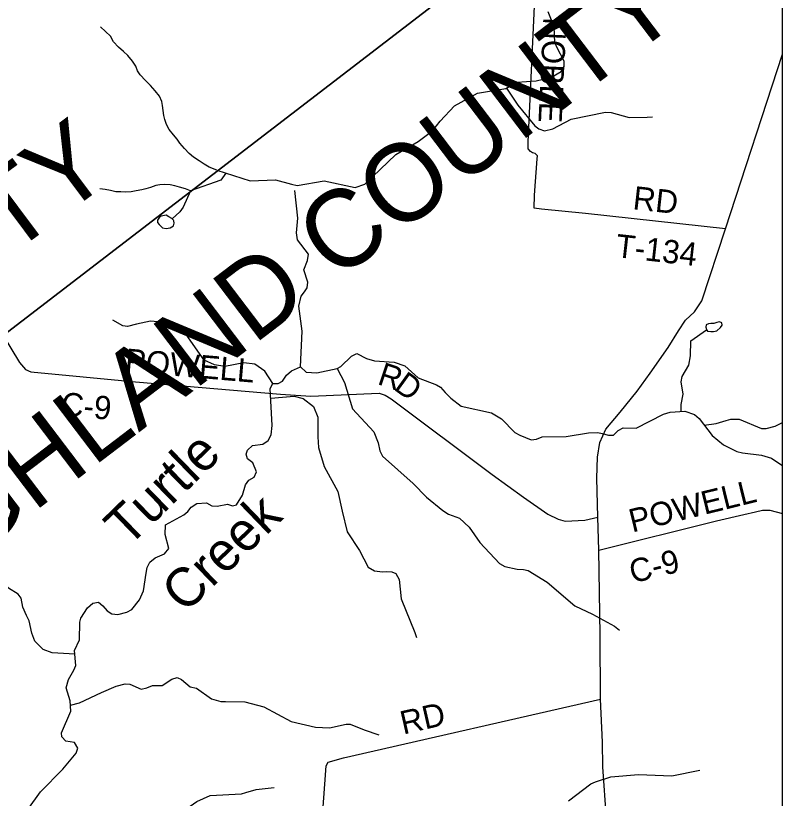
# Model space of a CAD drawing. Extents: x 0 to 1052, y -194 to 246.
# Drawn here: x 6.909 to 8.782, y 17.846 to 19.757 of the extents above; entities that cross this region are included whole.
import ezdxf

# ---------------------------------------------------------------- set-up
doc = ezdxf.new("R2010")
doc.units = 0
for name, color, linetype in [('GM_X_Corporation', 7, 'Continuous'), ('GM_X_County_Road', 7, 'Continuous'), ('GM_X_County_Road_Text', 7, 'Continuous'), ('GM_X_County_Text', 7, 'Continuous'), ('GM_X_Minor_Lake', 7, 'Continuous'), ('GM_X_Minor_River', 7, 'Continuous'), ('GM_X_Minor_River_Text', 7, 'Continuous'), ('GM_X_Township_Road', 7, 'Continuous'), ('GM_X_Township_Road_Text', 7, 'Continuous')]:
    doc.layers.add(name, color=color, linetype=linetype)

msp = doc.modelspace()

# ---------------------------------------------------------------- linework, layer by layer
at = {"layer": 'GM_X_Corporation'}
for points in [[(5.1788, 17.6981), (5.491, 17.9457), (6.1888, 18.4644), (6.5994, 18.7694), (6.8785, 18.9763), (8.1871, 19.9814), (8.6571, 20.341), (8.7822, 20.435), (8.7822, 21.0055), (1.9822, 21.0055), (1.9822, 14.2055)], [(8.7822, 14.2055), (8.7822, 20.435), (8.6571, 20.341), (8.1871, 19.9814), (6.8785, 18.9763), (6.5994, 18.7694), (6.1888, 18.4644), (5.491, 17.9457), (5.1788, 17.6981)], [(8.7822, 14.2055), (8.7822, 19.8853), (8.7716, 19.9458), (8.7665, 19.9791), (8.7595, 20.0343), (8.7564, 20.0663), (8.7504, 20.1046), (8.7444, 20.1332), (8.7375, 20.1583), (8.7292, 20.1831), (8.7137, 20.2216), (8.6781, 20.298), (8.6571, 20.341), (8.1871, 19.9814), (6.8785, 18.9763), (6.5994, 18.7694), (6.1888, 18.4644), (5.491, 17.9457), (5.1788, 17.6981)]]:
    msp.add_lwpolyline(points, dxfattribs=at)
msp.add_lwpolyline([(8.7822, 20.435), (8.7822, 21.0055), (5.5898, 21.0055), (5.6935, 20.5776), (5.9283, 19.6076), (5.992, 19.3448), (6.152, 18.6129), (6.1888, 18.4644), (6.5994, 18.7694), (6.8785, 18.9763), (8.1871, 19.9814), (8.6571, 20.341)], close=True, dxfattribs=at)
at = {"layer": 'GM_X_County_Road'}
msp.add_line((8.3338, 18.4518), (8.3315, 18.5323), dxfattribs=at)
for points in [[(8.3315, 18.5323), (8.329, 18.6276), (8.3307, 18.6788), (8.3358, 18.7147), (8.3511, 18.747), (8.3856, 18.7889), (8.4271, 18.8402), (8.4594, 18.8845), (8.5028, 18.9464), (8.5285, 18.9878), (8.5459, 19.0136), (8.5673, 19.0339), (8.5855, 19.0607), (8.6429, 19.2363), (8.7822, 19.6626)], [(6.8787, 18.9758), (6.9182, 18.9098), (6.933, 18.8934), (6.9457, 18.887), (7.2015, 18.8628), (7.5559, 18.8325), (7.6301, 18.8283), (7.7972, 18.8349), (7.8119, 18.8307), (7.8261, 18.8212), (8.0731, 18.6363), (8.1498, 18.5811), (8.209, 18.5397), (8.2345, 18.5273), (8.2518, 18.523), (8.2997, 18.5255), (8.3315, 18.5323)], [(8.3338, 18.4518), (8.6214, 18.5235), (8.6882, 18.5392), (8.7168, 18.5452), (8.734, 18.5493), (8.7514, 18.5496), (8.7822, 18.5411)], [(8.4426, 17.3326), (8.4083, 17.4853), (8.3741, 17.6521), (8.3656, 17.7047), (8.3552, 17.7703), (8.3521, 17.7958), (8.3437, 17.9231), (8.3426, 17.9831), (8.3378, 18.088), (8.3374, 18.2452), (8.3338, 18.4518)]]:
    msp.add_lwpolyline(points, dxfattribs=at)
at = {"layer": 'GM_X_Minor_Lake'}
for points in [[(7.2901, 19.2618), (7.2829, 19.2661), (7.2769, 19.2696), (7.2647, 19.2675), (7.2601, 19.2649), (7.2555, 19.2578), (7.2558, 19.2517), (7.2599, 19.2467), (7.2677, 19.239), (7.2768, 19.237), (7.2863, 19.2391), (7.2943, 19.2435), (7.2959, 19.2503)], [(7.2959, 19.2503), (7.2956, 19.2557), (7.2947, 19.2578), (7.2901, 19.2618)], [(8.5992, 18.9869), (8.6071, 18.9857), (8.6139, 18.9856), (8.6219, 18.9877), (8.6312, 18.9959), (8.6354, 19.0012), (8.634, 19.0073), (8.6283, 19.0096), (8.6222, 19.0074), (8.6146, 19.0057), (8.6078, 19.0054), (8.6013, 19.0047), (8.5964, 19.0018), (8.5955, 18.9961)], [(8.5955, 18.9961), (8.5965, 18.9903), (8.5975, 18.9889), (8.5992, 18.9869)]]:
    msp.add_lwpolyline(points, dxfattribs=at)
at = {"layer": 'GM_X_Minor_River'}
for points in [[(7.4008, 19.3794), (7.4818, 19.3533), (7.5437, 19.3561), (7.5829, 19.3452), (7.5965, 19.3424), (7.6627, 19.3538), (7.7383, 19.3371), (7.7619, 19.3459), (7.8374, 19.4179), (7.8921, 19.4493), (7.9285, 19.4764), (7.9459, 19.4996), (7.981, 19.5366), (8.0376, 19.5676), (8.1068, 19.5787), (8.1202, 19.5876), (8.1336, 19.5942), (8.181, 19.598), (8.218, 19.6069), (8.2417, 19.6206), (8.2487, 19.633), (8.2489, 19.6455), (8.2323, 19.678), (8.2265, 19.6913), (8.2244, 19.7293), (8.2102, 19.7659)], [(7.4008, 19.3794), (7.3819, 19.3872), (7.3694, 19.3945), (7.3574, 19.4026), (7.3438, 19.4111), (7.3325, 19.4203), (7.3212, 19.4325), (7.3103, 19.4459), (7.3032, 19.4554), (7.2942, 19.4658), (7.2837, 19.4788), (7.2773, 19.491), (7.2733, 19.5035), (7.2707, 19.5131), (7.2693, 19.5256), (7.2679, 19.5378), (7.2661, 19.5473), (7.2601, 19.5602), (7.25, 19.5732), (7.2387, 19.5862), (7.2259, 19.5985), (7.2135, 19.6123), (7.2068, 19.6226), (7.2023, 19.634), (7.1945, 19.6462), (7.1832, 19.66), (7.1723, 19.6692), (7.1602, 19.6799), (7.1482, 19.6933), (7.1404, 19.7067), (7.128, 19.7182), (7.1163, 19.73)], [(8.1082, 19.5796), (8.1357, 19.5388), (8.1774, 19.4881), (8.1872, 19.4803), (8.2007, 19.4759), (8.2213, 19.4806), (8.2664, 19.5045), (8.3497, 19.5214), (8.3641, 19.5208), (8.4075, 19.5084), (8.4515, 19.5092), (8.4648, 19.5101)], [(7.4221, 19.3725), (7.4098, 19.3555), (7.336, 19.3295)], [(7.336, 19.3295), (7.3237, 19.3342), (7.309, 19.3381), (7.2976, 19.3412), (7.2863, 19.3436), (7.2726, 19.3445), (7.2612, 19.3439), (7.2513, 19.342), (7.238, 19.3376), (7.227, 19.3339), (7.2171, 19.3321), (7.2034, 19.3296), (7.1909, 19.3267), (7.1783, 19.3256), (7.1655, 19.3265), (7.1537, 19.327), (7.1408, 19.3301), (7.1276, 19.3325), (7.1143, 19.3338)], [(7.336, 19.3295), (7.3182, 19.2894), (7.31, 19.2778), (7.2912, 19.2608)], [(7.6051, 18.8992), (7.6088, 18.9864), (7.601, 19.0476), (7.6063, 19.0722), (7.6145, 19.083), (7.6211, 19.0928), (7.6224, 19.1064), (7.6126, 19.1362), (7.6217, 19.1592), (7.6242, 19.1743), (7.5979, 19.21), (7.5951, 19.2271), (7.5983, 19.2623), (7.5907, 19.3299)], [(7.5374, 18.8589), (7.5178, 18.8888), (7.4934, 18.9059), (7.4661, 18.909), (7.4198, 18.9006), (7.3948, 18.9048), (7.3692, 18.9162), (7.3258, 18.9783), (7.3011, 18.9973), (7.2736, 19.0076), (7.238, 19.0112), (7.2041, 19.0041), (7.182, 18.9984), (7.1707, 18.9997), (7.1466, 19.0133)], [(8.5353, 18.791), (8.5353, 18.8078), (8.5402, 18.8331), (8.535, 18.8628), (8.5371, 18.876), (8.5535, 18.9034), (8.5576, 18.9265), (8.5586, 18.9633), (8.5969, 18.9896)], [(7.5261, 18.7195), (7.5328, 18.7335), (7.5354, 18.7566), (7.5308, 18.8469), (7.5374, 18.8589), (7.5503, 18.8591), (7.5606, 18.8643), (7.5703, 18.8793), (7.5826, 18.8901), (7.6051, 18.8992), (7.6186, 18.8869), (7.6444, 18.885), (7.6942, 18.8952), (7.7037, 18.9004), (7.7292, 18.9257), (7.7425, 18.932), (7.7659, 18.9199), (7.7855, 18.9146), (7.834, 18.9112), (7.8596, 18.9017), (7.8925, 18.8731), (7.937, 18.8554), (7.9467, 18.8499), (7.9583, 18.8365), (7.9721, 18.8234), (7.9972, 18.8036), (8.0713, 18.7873), (8.0957, 18.7729), (8.1289, 18.739), (8.1406, 18.7331), (8.1681, 18.7217), (8.1817, 18.7226), (8.1951, 18.7285), (8.2539, 18.7295), (8.3082, 18.7381), (8.3317, 18.7389), (8.3423, 18.7372), (8.357, 18.7324), (8.3699, 18.7326), (8.3811, 18.7442), (8.393, 18.7504), (8.4252, 18.7496), (8.4921, 18.7842), (8.5081, 18.7889), (8.5441, 18.7917), (8.5679, 18.7834), (8.5791, 18.7733), (8.6103, 18.7323), (8.638, 18.7095), (8.6708, 18.693), (8.6847, 18.6894), (8.7309, 18.6841), (8.7558, 18.6769), (8.7806, 18.6595), (8.7822, 18.658)], [(7.6942, 18.8952), (7.7126, 18.8611), (7.7317, 18.7971), (7.7843, 18.7409), (7.7945, 18.7139), (7.7987, 18.6941), (7.8053, 18.6814), (7.8805, 18.6147), (7.913, 18.5815), (7.9526, 18.5491), (7.9665, 18.5401), (7.9933, 18.5302), (8.0168, 18.5082), (8.0432, 18.4703), (8.0913, 18.4198), (8.1044, 18.4117), (8.1339, 18.4059), (8.1494, 18.4045), (8.1615, 18.4024), (8.2077, 18.3737), (8.275, 18.3157), (8.3179, 18.2957), (8.3721, 18.2668), (8.3841, 18.2564)], [(7.532, 18.8233), (7.5896, 18.8282), (7.6115, 18.8221), (7.6362, 18.8028), (7.6472, 18.7764), (7.6472, 18.7283), (7.6487, 18.7025), (7.6624, 18.656), (7.6959, 18.5948), (7.7065, 18.5468), (7.7186, 18.4966), (7.7486, 18.4513), (7.77, 18.4108), (7.7854, 18.4011), (7.8054, 18.3993), (7.8149, 18.3999), (7.8278, 18.3993), (7.838, 18.3946), (7.8461, 18.3804), (7.8507, 18.3333), (7.8839, 18.2513), (7.8886, 18.2387)], [(8.5913, 18.7573), (8.6203, 18.7609), (8.6446, 18.7689), (8.6564, 18.7718), (8.6765, 18.7714), (8.7312, 18.7494), (8.7422, 18.7488), (8.7642, 18.7545), (8.7822, 18.7634)], [(7.0535, 18.1981), (6.9981, 18.201), (6.9759, 18.2096), (6.9561, 18.2301), (6.9484, 18.2491), (6.9421, 18.2796), (6.9355, 18.2922), (6.9263, 18.3124), (6.9225, 18.3349), (6.9151, 18.3445), (6.8914, 18.3593), (6.8833, 18.3723), (6.869, 18.4559), (6.8525, 18.5101), (6.8344, 18.5437), (6.8018, 18.5928), (6.7929, 18.6267), (6.79, 18.64), (6.7834, 18.6731), (6.7881, 18.7367), (6.7861, 18.75)], [(6.939, 17.8192), (6.9692, 17.8616), (7.0243, 17.9176), (7.0568, 17.9565), (7.0612, 17.9686), (7.0523, 17.982), (7.0315, 17.9858), (7.0214, 17.9962), (7.0212, 18.006), (7.044, 18.0588), (7.0418, 18.0838), (7.0324, 18.1162), (7.038, 18.1362), (7.0509, 18.1592), (7.0556, 18.1701), (7.0528, 18.2069), (7.0646, 18.2333), (7.0653, 18.2758), (7.0681, 18.2856), (7.0844, 18.3111), (7.0975, 18.3227), (7.1112, 18.3247), (7.122, 18.3162), (7.1328, 18.3039), (7.1441, 18.2969), (7.1585, 18.2948), (7.1809, 18.3005), (7.1924, 18.3075), (7.2114, 18.3311), (7.2216, 18.3526), (7.2279, 18.3961), (7.23, 18.4094), (7.2371, 18.4225), (7.2501, 18.4329), (7.2727, 18.4432), (7.2835, 18.4559), (7.2738, 18.4902), (7.2753, 18.5137), (7.32, 18.5384), (7.3296, 18.5466), (7.3381, 18.5571), (7.3516, 18.566), (7.3751, 18.5675), (7.3882, 18.5605), (7.4015, 18.5592), (7.4262, 18.5645), (7.4387, 18.5601), (7.4482, 18.5626), (7.4634, 18.5866), (7.4706, 18.6116), (7.4783, 18.6228), (7.4917, 18.6302), (7.4972, 18.643), (7.4881, 18.6648), (7.4757, 18.6748), (7.4721, 18.6863), (7.4757, 18.6961), (7.4872, 18.7073), (7.5127, 18.7107), (7.5261, 18.7195)], [(7.0427, 18.0734), (7.0652, 18.0793), (7.1183, 18.1046), (7.1546, 18.12), (7.1766, 18.1253), (7.188, 18.1244), (7.2159, 18.113), (7.2292, 18.1158), (7.2429, 18.1217), (7.2668, 18.1217), (7.2902, 18.1372), (7.3035, 18.1408), (7.3144, 18.1361), (7.3354, 18.1183), (7.3509, 18.115), (7.3873, 18.0887), (7.4099, 18.0826), (7.4217, 18.0821), (7.469, 18.0817), (7.5155, 18.0692), (7.582, 18.0333), (7.6413, 18.0199), (7.6758, 18.0178), (7.7165, 18.0274), (7.7264, 18.0269), (7.7607, 18.0131), (7.7965, 18.0015)], [(8.2596, 17.8403), (8.3145, 17.8816), (8.3255, 17.8864), (8.3632, 17.8983), (8.4308, 17.9044), (8.5123, 17.9009), (8.5804, 17.9146)], [(6.9537, 17.6461), (6.9832, 17.6873), (7.0062, 17.7036), (7.0895, 17.7201), (7.1277, 17.74), (7.1491, 17.7518), (7.2258, 17.7806), (7.2711, 17.7893), (7.3028, 17.804), (7.3515, 17.8382), (7.3843, 17.8528), (7.4609, 17.8569), (7.4716, 17.8606), (7.4968, 17.8674), (7.5404, 17.8728)]]:
    msp.add_lwpolyline(points, dxfattribs=at)
at = {"layer": 'GM_X_Township_Road'}
for points in [[(8.6429, 19.2363), (8.3009, 19.274), (8.1934, 19.2844), (8.176, 19.2868), (8.1769, 19.319), (8.183, 19.4077), (8.1836, 19.4145), (8.1784, 19.4203), (8.1716, 19.422), (8.1664, 19.4256), (8.1609, 19.4318), (8.1609, 19.4485), (8.1807, 19.8678), (8.1873, 19.9809)], [(7.6288, 17.3894), (7.6677, 17.9258), (7.6728, 17.9344), (7.7095, 17.9452), (8.3378, 18.088)]]:
    msp.add_lwpolyline(points, dxfattribs=at)

# ---------------------------------------------------------------- texts
at = {"layer": 'GM_X_County_Road_Text'}
for s, height, rotation, p in [('POWELL', 0.05682, 355.1129, (7.1746, 18.8879)), ('R', 0.0568, 341.4182, (7.7902, 18.858)), ('D', 0.0568, 324.2464, (7.8305, 18.8452)), ('C-9', 0.05682, 354.4738, (7.018, 18.7816)), ('POWELL', 0.05682, 13.8309, (8.4155, 18.4949)), ('C-9', 0.05682, 13.9242, (8.4163, 18.3707))]:
    msp.add_text(s, height=height, rotation=rotation, dxfattribs=at).set_placement(p)
at = {"layer": 'GM_X_County_Text'}
for s, rotation, p in [('HIGHLAND COUNTY', 37.2438, (6.5935, 18.2705)), ('CLINTON COUNTY', 36.7754, (5.3509, 18.0148))]:
    msp.add_text(s, height=0.189394, rotation=rotation, dxfattribs=at).set_placement(p)
at = {"layer": 'GM_X_Minor_River_Text'}
for s, rotation, p in [('Turtle', 44.1863, (7.1833, 18.4564)), ('Creek', 43.9898, (7.3224, 18.2953))]:
    msp.add_text(s, height=0.0947, rotation=rotation, dxfattribs=at).set_placement(p)
at = {"layer": 'GM_X_Township_Road_Text'}
for s, rotation, p in [('NOBLE', 267.3225, (8.1982, 19.7538)), ('RD', 353.5502, (8.415, 19.2846)), ('T-134', 353.5362, (8.3731, 19.1677)), ('RD', 12.9561, (7.8559, 18.0017))]:
    msp.add_text(s, height=0.05682, rotation=rotation, dxfattribs=at).set_placement(p)

doc.saveas('drawing.dxf')
